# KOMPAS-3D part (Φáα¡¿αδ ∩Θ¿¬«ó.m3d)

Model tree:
1. Эскиз:1
2. Операция выдавливания:1
     Расстояние 1 = 0.1
3. Эскиз:2
4. Операция выдавливания:2
     Расстояние 1 = 1.8
5. Эскиз:3
6. Вырезать элемент выдавливания:1
     Расстояние 1 = 7
7. Скругление:1
     Радиус = 0.5
8. Эскиз:4
9. Вырезать элемент выдавливания:2
     Расстояние 1 = 7
10. Скругление:2
     Радиус = 0.5
11. Эскиз:5
12. Операция выдавливания:3
     Расстояние 1 = 0.1
13. Эскиз:6
14. Операция выдавливания:4
     Расстояние 1 = 0.1; Расстояние 2 = 4.9

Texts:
  Сплав АЛ8  ГОСТ 1583-93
